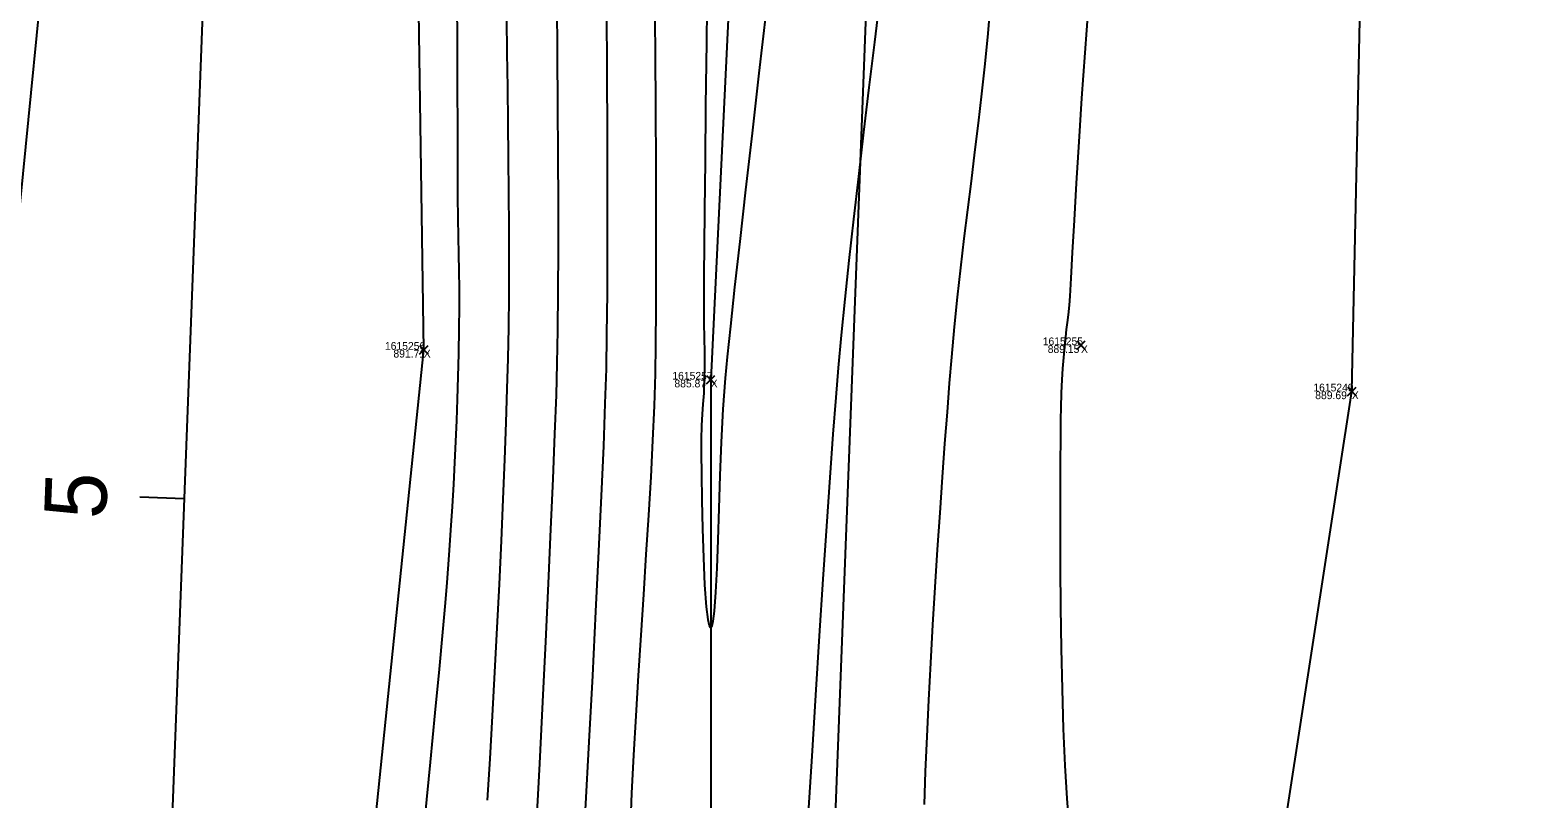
# Model space of a CAD drawing. Extents: x 1957117 to 1971063, y 701601 to 715861.
# Drawn here: x 1962709.8 to 1962778, y 702484.4 to 702519.1 of the extents above; entities that cross this region are included whole.
import ezdxf

# ---------------------------------------------------------------- set-up
doc = ezdxf.new("R2010")
doc.units = 0
for name, color, linetype in [('AP_X_Lights', 7, 'Continuous'), ('DT_X_Break_Line', 7, 'Continuous'), ('DT_X_Contour_Major', 7, 'Continuous'), ('DT_X_Contour_Minor', 7, 'Continuous'), ('DT_X_TIN_Hull', 7, 'Continuous'), ('GE_X_CL_20', 7, 'Continuous'), ('PV_P_Shoulder', 7, 'Continuous'), ('RS_Raster1', 7, 'Continuous'), ('RW_X_Esmt_RR', 7, 'Continuous'), ('SC_Scratch1', 7, 'Continuous')]:
    doc.layers.add(name, color=color, linetype=linetype)

msp = doc.modelspace()

# ---------------------------------------------------------------- linework, layer by layer
at = {"layer": 'AP_X_Lights'}
for p, q in [((1962757.183, 702504.666), (1962757.571, 702505.056)), ((1962757.183, 702505.056), (1962757.571, 702504.666)), ((1962727.448, 702504.458), (1962727.836, 702504.848)), ((1962727.448, 702504.848), (1962727.836, 702504.458)), ((1962740.429, 702503.107), (1962740.817, 702503.497)), ((1962740.429, 702503.497), (1962740.817, 702503.107)), ((1962769.431, 702502.576), (1962769.819, 702502.966)), ((1962769.431, 702502.966), (1962769.819, 702502.576))]:
    msp.add_line(p, q, dxfattribs=at)
at = {"layer": 'DT_X_Break_Line'}
for points in [[(1962712.212, 702702.955), (1962716.271, 702654.75), (1962711.053, 702609.737), (1962713.646, 702554.428), (1962708.781, 702505.283), (1962707.233, 702455.469), (1962704.944, 702406.927), (1962695.192, 702355.079), (1962699.519, 702306.049), (1962692.358, 702256.103), (1962693.103, 702205.318), (1962697.09, 702154.707), (1962695.369, 702143.214), (1962687.557, 702105.709), (1962680.996, 702055.861)], [(1962752.132, 702702.919), (1962747.065, 702649.147), (1962745.48, 702606.97), (1962743.008, 702552.829), (1962740.623, 702503.302), (1962740.641, 702452.933), (1962736.982, 702403.388), (1962741.529, 702352.919), (1962733.397, 702302.963), (1962742.046, 702251.987), (1962742.053, 702202.145), (1962741.582, 702152.179), (1962738.197, 702102.408), (1962725.619, 702053.061)], [(1962713.582, 702053.996), (1962711.466, 702104.13), (1962714.937, 702203.608), (1962720.713, 702253.951), (1962719.889, 702303.145), (1962721.566, 702358.521), (1962719.193, 702407.367), (1962722.415, 702453.828), (1962727.642, 702504.653), (1962726.923, 702553.596), (1962728.43, 702603.611), (1962735.623, 702653.941), (1962730.179, 702698.673)]]:
    msp.add_lwpolyline(points, dxfattribs=at)
at = {"layer": 'DT_X_Contour_Major'}
msp.add_lwpolyline([(1962731.388, 702519.622), (1962731.406, 702518.077), (1962731.426, 702516.505), (1962731.446, 702514.918), (1962731.463, 702513.325), (1962731.478, 702511.737), (1962731.487, 702510.166), (1962731.49, 702508.621), (1962731.485, 702507.114), (1962731.471, 702505.656), (1962731.445, 702504.257), (1962731.409, 702502.895), (1962731.359, 702501.363), (1962731.296, 702499.687), (1962731.223, 702497.894), (1962731.139, 702496.01), (1962731.048, 702494.063), (1962730.95, 702492.078), (1962730.846, 702490.082), (1962730.739, 702488.101), (1962730.628, 702486.163), (1962730.517, 702484.293)], dxfattribs=at)
msp.add_lwpolyline([(1962731.388, 702519.622), (1962731.406, 702518.077), (1962731.426, 702516.505), (1962731.446, 702514.918), (1962731.463, 702513.325), (1962731.478, 702511.737), (1962731.487, 702510.166), (1962731.49, 702508.621), (1962731.485, 702507.114), (1962731.471, 702505.656), (1962731.445, 702504.257), (1962731.409, 702502.895), (1962731.359, 702501.363), (1962731.296, 702499.687), (1962731.223, 702497.894), (1962731.139, 702496.01), (1962731.048, 702494.063), (1962730.95, 702492.078), (1962730.846, 702490.082), (1962730.739, 702488.101), (1962730.628, 702486.163), (1962730.517, 702484.293)], dxfattribs=at)
at = {"layer": 'DT_X_Contour_Minor'}
for points in [[(1962740.463, 702521.631), (1962740.428, 702518.54), (1962740.396, 702515.692), (1962740.369, 702513.157), (1962740.346, 702511.001), (1962740.329, 702509.294), (1962740.317, 702508.102), (1962740.312, 702507.496), (1962740.313, 702506.63), (1962740.32, 702505.865), (1962740.33, 702505.176), (1962740.338, 702504.541), (1962740.34, 702503.934), (1962740.332, 702503.332), (1962740.307, 702502.698), (1962740.271, 702502.194), (1962740.234, 702501.735), (1962740.206, 702501.231), (1962740.194, 702500.597), (1962740.197, 702499.986), (1962740.206, 702499.035), (1962740.224, 702497.855), (1962740.253, 702496.554), (1962740.294, 702495.244), (1962740.35, 702494.033), (1962740.423, 702493.033), (1962740.494, 702492.457), (1962740.557, 702492.193), (1962740.603, 702492.11), (1962740.627, 702492.099), (1962740.649, 702492.107), (1962740.689, 702492.171), (1962740.742, 702492.377), (1962740.802, 702492.842), (1962740.862, 702493.689), (1962740.912, 702494.779), (1962740.956, 702496.058), (1962741, 702497.471), (1962741.05, 702498.963), (1962741.112, 702500.48), (1962741.191, 702501.965), (1962741.293, 702503.364), (1962741.385, 702504.334), (1962741.529, 702505.722), (1962741.721, 702507.477), (1962741.952, 702509.55), (1962742.216, 702511.888), (1962742.508, 702514.443), (1962742.82, 702517.163), (1962743.147, 702519.997)], [(1962740.463, 702521.631), (1962740.428, 702518.54), (1962740.396, 702515.692), (1962740.369, 702513.157), (1962740.346, 702511.001), (1962740.329, 702509.294), (1962740.317, 702508.102), (1962740.312, 702507.496), (1962740.313, 702506.63), (1962740.32, 702505.865), (1962740.33, 702505.176), (1962740.338, 702504.541), (1962740.34, 702503.934), (1962740.332, 702503.332), (1962740.307, 702502.698), (1962740.271, 702502.194), (1962740.234, 702501.735), (1962740.206, 702501.231), (1962740.194, 702500.597), (1962740.197, 702499.986), (1962740.206, 702499.035), (1962740.224, 702497.855), (1962740.253, 702496.554), (1962740.294, 702495.244), (1962740.35, 702494.033), (1962740.423, 702493.033), (1962740.494, 702492.457), (1962740.557, 702492.193), (1962740.603, 702492.11), (1962740.627, 702492.099), (1962740.649, 702492.107), (1962740.689, 702492.171), (1962740.742, 702492.377), (1962740.802, 702492.842), (1962740.862, 702493.689), (1962740.912, 702494.779), (1962740.956, 702496.058), (1962741, 702497.471), (1962741.05, 702498.963), (1962741.112, 702500.48), (1962741.191, 702501.965), (1962741.293, 702503.364), (1962741.385, 702504.334), (1962741.529, 702505.722), (1962741.721, 702507.477), (1962741.952, 702509.55), (1962742.216, 702511.888), (1962742.508, 702514.443), (1962742.82, 702517.163), (1962743.147, 702519.997)], [(1962738.085, 702520.79), (1962738.106, 702518.13), (1962738.123, 702515.522), (1962738.137, 702513.013), (1962738.145, 702510.649), (1962738.148, 702508.476), (1962738.144, 702506.54), (1962738.132, 702504.887), (1962738.11, 702503.564), (1962738.066, 702502.114), (1962737.998, 702500.555), (1962737.911, 702498.905), (1962737.809, 702497.181), (1962737.697, 702495.403), (1962737.579, 702493.588), (1962737.459, 702491.755), (1962737.341, 702489.922), (1962737.23, 702488.108), (1962737.129, 702486.33), (1962737.044, 702484.607), (1962736.977, 702482.957)], [(1962738.085, 702520.79), (1962738.106, 702518.13), (1962738.123, 702515.522), (1962738.137, 702513.013), (1962738.145, 702510.649), (1962738.148, 702508.476), (1962738.144, 702506.54), (1962738.132, 702504.887), (1962738.11, 702503.564), (1962738.066, 702502.114), (1962737.998, 702500.555), (1962737.911, 702498.905), (1962737.809, 702497.181), (1962737.697, 702495.403), (1962737.579, 702493.588), (1962737.459, 702491.755), (1962737.341, 702489.922), (1962737.23, 702488.108), (1962737.129, 702486.33), (1962737.044, 702484.607), (1962736.977, 702482.957)], [(1962727.703, 702483.553), (1962727.944, 702486.004), (1962728.162, 702488.239), (1962728.351, 702490.215), (1962728.508, 702491.887), (1962728.626, 702493.208), (1962728.702, 702494.134), (1962728.79, 702495.365), (1962728.869, 702496.505), (1962728.937, 702497.57), (1962728.997, 702498.579), (1962729.049, 702499.551), (1962729.095, 702500.503), (1962729.134, 702501.455), (1962729.168, 702502.424), (1962729.197, 702503.429), (1962729.224, 702504.488), (1962729.245, 702505.609), (1962729.253, 702506.573), (1962729.253, 702507.424), (1962729.245, 702508.209), (1962729.232, 702508.972), (1962729.217, 702509.757), (1962729.203, 702510.609), (1962729.192, 702511.573), (1962729.185, 702512.694), (1962729.183, 702513.527), (1962729.179, 702514.781), (1962729.174, 702516.408), (1962729.168, 702518.361), (1962729.161, 702520.593)], [(1962727.703, 702483.553), (1962727.944, 702486.004), (1962728.162, 702488.239), (1962728.351, 702490.215), (1962728.508, 702491.887), (1962728.626, 702493.208), (1962728.702, 702494.134), (1962728.79, 702495.365), (1962728.869, 702496.505), (1962728.937, 702497.57), (1962728.997, 702498.579), (1962729.049, 702499.551), (1962729.095, 702500.503), (1962729.134, 702501.455), (1962729.168, 702502.424), (1962729.197, 702503.429), (1962729.224, 702504.488), (1962729.245, 702505.609), (1962729.253, 702506.573), (1962729.253, 702507.424), (1962729.245, 702508.209), (1962729.232, 702508.972), (1962729.217, 702509.757), (1962729.203, 702510.609), (1962729.192, 702511.573), (1962729.185, 702512.694), (1962729.183, 702513.527), (1962729.179, 702514.781), (1962729.174, 702516.408), (1962729.168, 702518.361), (1962729.161, 702520.593)], [(1962733.662, 702520.327), (1962733.682, 702518.006), (1962733.699, 702515.699), (1962733.711, 702513.438), (1962733.718, 702511.257), (1962733.718, 702509.192), (1962733.71, 702507.276), (1962733.694, 702505.542), (1962733.667, 702504.026), (1962733.627, 702502.605), (1962733.565, 702500.856), (1962733.483, 702498.822), (1962733.384, 702496.549), (1962733.272, 702494.081), (1962733.147, 702491.463), (1962733.014, 702488.739), (1962732.874, 702485.955), (1962732.729, 702483.154)], [(1962733.662, 702520.327), (1962733.682, 702518.006), (1962733.699, 702515.699), (1962733.711, 702513.438), (1962733.718, 702511.257), (1962733.718, 702509.192), (1962733.71, 702507.276), (1962733.694, 702505.542), (1962733.667, 702504.026), (1962733.627, 702502.605), (1962733.565, 702500.856), (1962733.483, 702498.822), (1962733.384, 702496.549), (1962733.272, 702494.081), (1962733.147, 702491.463), (1962733.014, 702488.739), (1962732.874, 702485.955), (1962732.729, 702483.154)], [(1962735.917, 702520.029), (1962735.931, 702517.167), (1962735.941, 702514.412), (1962735.945, 702511.809), (1962735.943, 702509.401), (1962735.933, 702507.234), (1962735.915, 702505.35), (1962735.889, 702503.795), (1962735.842, 702502.223), (1962735.769, 702500.291), (1962735.672, 702498.048), (1962735.554, 702495.542), (1962735.419, 702492.822), (1962735.27, 702489.935), (1962735.112, 702486.931), (1962734.946, 702483.857)], [(1962735.917, 702520.029), (1962735.931, 702517.167), (1962735.941, 702514.412), (1962735.945, 702511.809), (1962735.943, 702509.401), (1962735.933, 702507.234), (1962735.915, 702505.35), (1962735.889, 702503.795), (1962735.842, 702502.223), (1962735.769, 702500.291), (1962735.672, 702498.048), (1962735.554, 702495.542), (1962735.419, 702492.822), (1962735.27, 702489.935), (1962735.112, 702486.931), (1962734.946, 702483.857)], [(1962745.039, 702483.478), (1962745.209, 702486.277), (1962745.381, 702489.039), (1962745.551, 702491.722), (1962745.718, 702494.284), (1962745.878, 702496.684), (1962746.029, 702498.881), (1962746.169, 702500.834), (1962746.295, 702502.501), (1962746.404, 702503.84), (1962746.539, 702505.317), (1962746.702, 702506.943), (1962746.89, 702508.696), (1962747.097, 702510.553), (1962747.321, 702512.49), (1962747.555, 702514.485), (1962747.797, 702516.515), (1962748.042, 702518.556), (1962748.286, 702520.585)], [(1962745.039, 702483.478), (1962745.209, 702486.277), (1962745.381, 702489.039), (1962745.551, 702491.722), (1962745.718, 702494.284), (1962745.878, 702496.684), (1962746.029, 702498.881), (1962746.169, 702500.834), (1962746.295, 702502.501), (1962746.404, 702503.84), (1962746.539, 702505.317), (1962746.702, 702506.943), (1962746.89, 702508.696), (1962747.097, 702510.553), (1962747.321, 702512.49), (1962747.555, 702514.485), (1962747.797, 702516.515), (1962748.042, 702518.556), (1962748.286, 702520.585)], [(1962753.254, 702520.053), (1962753.158, 702518.947), (1962753.021, 702517.573), (1962752.875, 702516.226), (1962752.721, 702514.899), (1962752.563, 702513.586), (1962752.401, 702512.283), (1962752.24, 702510.982), (1962752.08, 702509.678), (1962751.926, 702508.365), (1962751.778, 702507.038), (1962751.64, 702505.69), (1962751.515, 702504.315), (1962751.417, 702503.147), (1962751.314, 702501.839), (1962751.205, 702500.413), (1962751.095, 702498.888), (1962750.983, 702497.285), (1962750.872, 702495.624), (1962750.764, 702493.926), (1962750.66, 702492.211), (1962750.563, 702490.5), (1962750.474, 702488.813), (1962750.396, 702487.17), (1962750.329, 702485.592), (1962750.276, 702484.098)], [(1962753.254, 702520.053), (1962753.158, 702518.947), (1962753.021, 702517.573), (1962752.875, 702516.226), (1962752.721, 702514.899), (1962752.563, 702513.586), (1962752.401, 702512.283), (1962752.24, 702510.982), (1962752.08, 702509.678), (1962751.926, 702508.365), (1962751.778, 702507.038), (1962751.64, 702505.69), (1962751.515, 702504.315), (1962751.417, 702503.147), (1962751.314, 702501.839), (1962751.205, 702500.413), (1962751.095, 702498.888), (1962750.983, 702497.285), (1962750.872, 702495.624), (1962750.764, 702493.926), (1962750.66, 702492.211), (1962750.563, 702490.5), (1962750.474, 702488.813), (1962750.396, 702487.17), (1962750.329, 702485.592), (1962750.276, 702484.098)], [(1962757.697, 702520.122), (1962757.545, 702518.072), (1962757.404, 702516.029), (1962757.276, 702514.049), (1962757.162, 702512.189), (1962757.062, 702510.506), (1962756.979, 702509.055), (1962756.912, 702507.894), (1962756.864, 702507.079), (1962756.836, 702506.666), (1962756.791, 702506.231), (1962756.749, 702505.886), (1962756.708, 702505.571), (1962756.667, 702505.226), (1962756.626, 702504.791), (1962756.584, 702504.301), (1962756.545, 702503.81), (1962756.511, 702503.288), (1962756.483, 702502.703), (1962756.462, 702502.022), (1962756.454, 702501.523), (1962756.445, 702500.674), (1962756.437, 702499.529), (1962756.432, 702498.137), (1962756.432, 702496.552), (1962756.439, 702494.824), (1962756.454, 702493.005), (1962756.48, 702491.148), (1962756.518, 702489.303), (1962756.571, 702487.523), (1962756.641, 702485.859), (1962756.729, 702484.362), (1962756.83, 702483.17)], [(1962757.697, 702520.122), (1962757.545, 702518.072), (1962757.404, 702516.029), (1962757.276, 702514.049), (1962757.162, 702512.189), (1962757.062, 702510.506), (1962756.979, 702509.055), (1962756.912, 702507.894), (1962756.864, 702507.079), (1962756.836, 702506.666), (1962756.791, 702506.231), (1962756.749, 702505.886), (1962756.708, 702505.571), (1962756.667, 702505.226), (1962756.626, 702504.791), (1962756.584, 702504.301), (1962756.545, 702503.81), (1962756.511, 702503.288), (1962756.483, 702502.703), (1962756.462, 702502.022), (1962756.454, 702501.523), (1962756.445, 702500.674), (1962756.437, 702499.529), (1962756.432, 702498.137), (1962756.432, 702496.552), (1962756.439, 702494.824), (1962756.454, 702493.005), (1962756.48, 702491.148), (1962756.518, 702489.303), (1962756.571, 702487.523), (1962756.641, 702485.859), (1962756.729, 702484.362), (1962756.83, 702483.17)]]:
    msp.add_lwpolyline(points, dxfattribs=at)
at = {"layer": 'DT_X_TIN_Hull'}
msp.add_lwpolyline([(1962757.576, 702251.621), (1962759.026, 702351.713), (1962754.137, 702402.367), (1962769.625, 702502.771), (1962771.847, 702605.545), (1962775.888, 702647.495), (1962778.042, 702697.695)], dxfattribs=at)
at = {"layer": 'GE_X_CL_20'}
msp.add_line((1962716.801, 702497.908), (1962714.803, 702497.984), dxfattribs=at)
msp.add_lwpolyline([(1962741.373, 703141.619), (1962697.729, 701998.272)], dxfattribs=at)
at = {"layer": 'RW_X_Esmt_RR'}
msp.add_lwpolyline([(1962729.176, 702035.621), (1962771.351, 703140.475)], dxfattribs=at)

# ---------------------------------------------------------------- texts
at = {"layer": 'GE_X_CL_20'}
msp.add_text('5', height=2.8, rotation=87.81394, dxfattribs=at).set_placement((1962713.263, 702496.976))
at = {"layer": 'PV_P_Shoulder'}
for s, p in [('891.71', (1962726.272, 702504.303)), ('889.15', (1962755.87, 702504.511)), ('885.87', (1962738.983, 702502.952)), ('889.69', (1962767.972, 702502.421))]:
    msp.add_text(s, height=0.35, dxfattribs=at).set_placement(p)
at = {"layer": 'RS_Raster1'}
for s, p in [('1615256', (1962725.887, 702504.653)), ('1615255', (1962755.644, 702504.861)), ('1615257', (1962738.89, 702503.302)), ('1615249', (1962767.886, 702502.771))]:
    msp.add_text(s, height=0.35, dxfattribs=at).set_placement(p)
at = {"layer": 'SC_Scratch1'}
for p in [(1962727.642, 702504.303), (1962757.377, 702504.511), (1962740.623, 702502.952), (1962769.625, 702502.421)]:
    msp.add_text('X', height=0.35, dxfattribs=at).set_placement(p)

doc.saveas('drawing.dxf')
